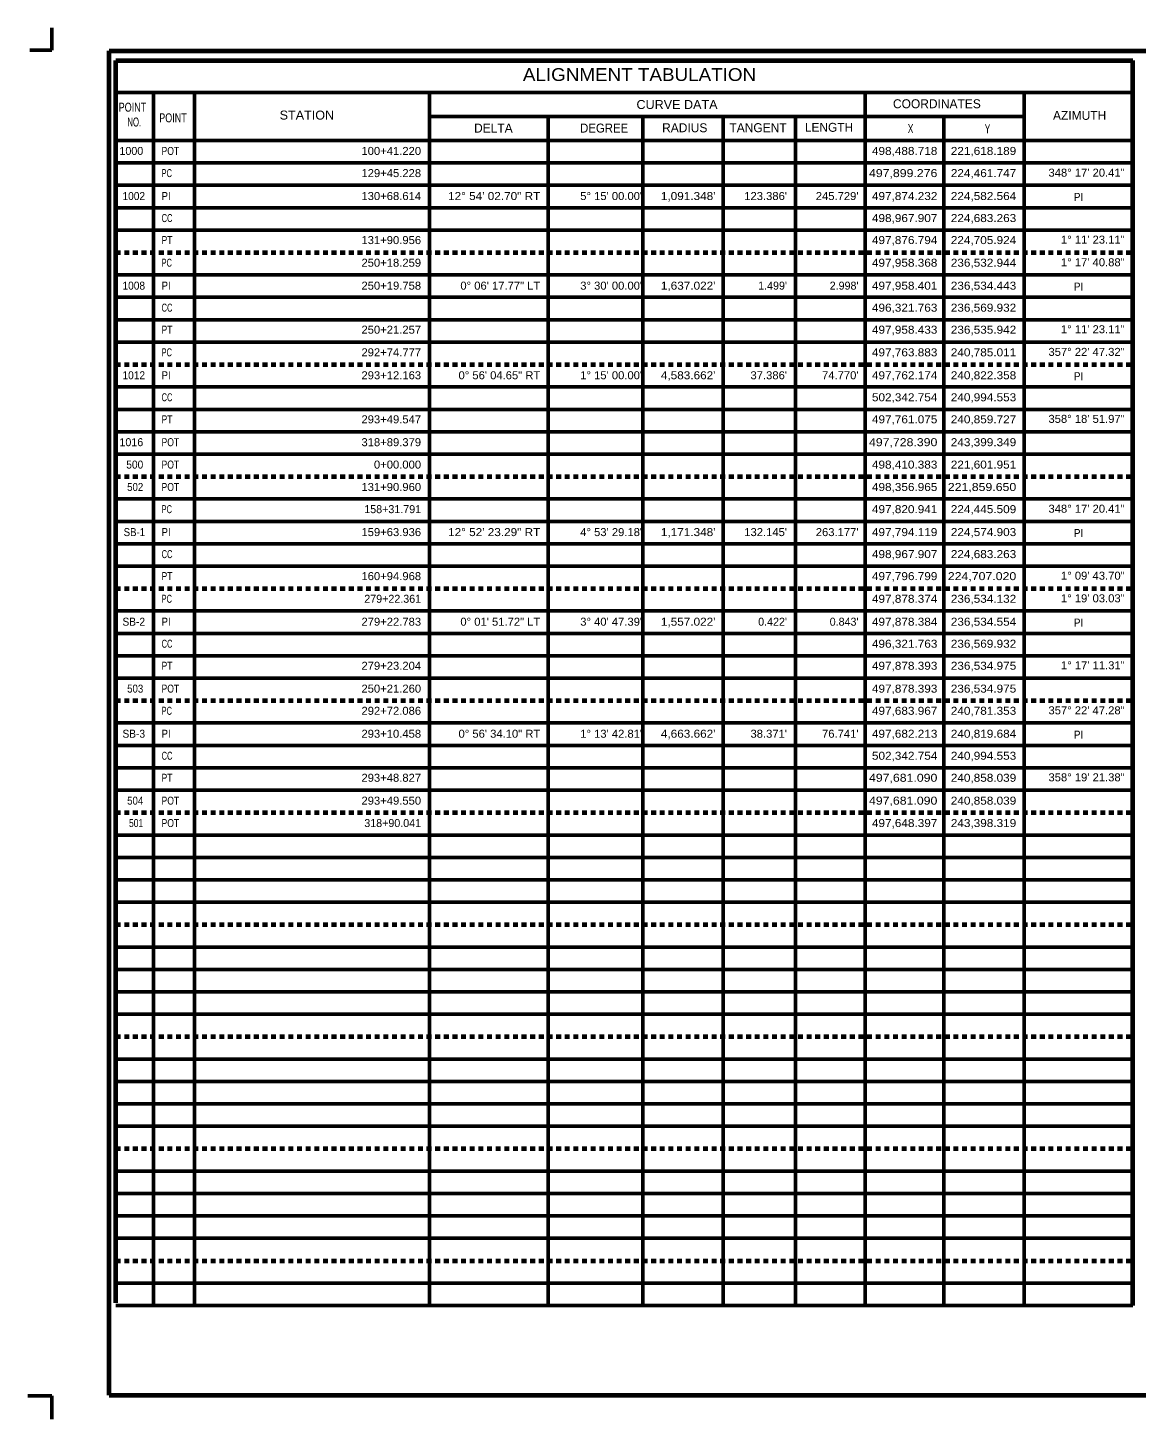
# Model space of a CAD drawing. Extents: x 22753 to 24440, y 5712 to 6801.
# Drawn here: x 22753 to 23619, y 5712 to 6799 of the extents above; entities that cross this region are included whole.
import ezdxf
from ezdxf.enums import TextEntityAlignment as Align

# ---------------------------------------------------------------- set-up
doc = ezdxf.new("R2010")
doc.units = 0
doc.header["$LTSCALE"] = 2.5
doc.linetypes.add('SHORT_DASHED', pattern=[2.7, 1.5, -1.2])
doc.layers.add('2', color=7, linetype='Continuous')
doc.layers.add('57', color=7, linetype='Continuous')
doc.layers.add('27', color=7, linetype='Continuous', lineweight=53)
doc.layers.add('63', color=7, linetype='Continuous', lineweight=70)

msp = doc.modelspace()

# ---------------------------------------------------------------- linework, layer by layer
at = {"layer": '27', "lineweight": 70}
for p, q in [((22821.896, 6773.426), (23616.896, 6773.426)), ((22821.896, 5803.105), (22821.896, 6773.426))]:
    msp.add_line(p, q, dxfattribs=at)
at = {"layer": '27'}
for p, q in [((22821.896, 6748.376), (23616.896, 6748.376)), ((22851.446, 6747.026), (22851.446, 5800.976)), ((22883.346, 6747.376), (22883.346, 5800.976)), ((23067.096, 6747.676), (23067.096, 5800.976)), ((23407.496, 6748.476), (23407.496, 5800.976)), ((23531.896, 6748.376), (23531.896, 5800.976)), ((23067.096, 6729.726), (23531.896, 6729.726)), ((23159.946, 6729.726), (23159.946, 5800.976)), ((23233.823, 6729.726), (23233.823, 5800.976)), ((23296.646, 6729.726), (23296.646, 5800.976)), ((23353.096, 6729.726), (23353.096, 5800.976)), ((23469.196, 6729.726), (23469.196, 5800.976)), ((22821.896, 6710.976), (23616.896, 6710.976)), ((22821.896, 6693.476), (23616.896, 6693.476)), ((22821.896, 6675.976), (23616.896, 6675.976)), ((22821.896, 6658.476), (23616.896, 6658.476)), ((22821.896, 6658.476), (23616.896, 6658.476)), ((22821.896, 6640.976), (23616.896, 6640.976)), ((22821.896, 6605.976), (23616.896, 6605.976)), ((22821.896, 6588.476), (23616.896, 6588.476)), ((22821.896, 6570.976), (23616.896, 6570.976)), ((22821.896, 6553.476), (23616.896, 6553.476)), ((22821.896, 6518.476), (23616.896, 6518.476)), ((22821.896, 6500.976), (23616.896, 6500.976)), ((22821.896, 6483.476), (23616.896, 6483.476)), ((22821.896, 6465.976), (23616.896, 6465.976)), ((22821.896, 6430.976), (23616.896, 6430.976)), ((22821.896, 6413.476), (23616.896, 6413.476)), ((22821.896, 6395.976), (23616.896, 6395.976)), ((22821.896, 6378.476), (23616.896, 6378.476)), ((22821.896, 6343.476), (23616.896, 6343.476)), ((22821.896, 6325.976), (23616.896, 6325.976)), ((22821.896, 6308.476), (23616.896, 6308.476)), ((22821.896, 6290.976), (23616.896, 6290.976)), ((22821.896, 6255.976), (23616.896, 6255.976)), ((22821.896, 6238.476), (23616.896, 6238.476)), ((22821.896, 6220.976), (23616.896, 6220.976)), ((22821.896, 6203.476), (23616.896, 6203.476)), ((22821.896, 6168.476), (23616.896, 6168.476)), ((22821.896, 6150.976), (23616.896, 6150.976)), ((22821.896, 6133.476), (23616.896, 6133.476)), ((22821.896, 6115.976), (23616.896, 6115.976)), ((22821.896, 6080.976), (23616.896, 6080.976)), ((22821.896, 6063.476), (23616.896, 6063.476)), ((22821.896, 6045.976), (23616.896, 6045.976)), ((22821.896, 6028.476), (23616.896, 6028.476)), ((22821.896, 5993.476), (23616.896, 5993.476)), ((22821.896, 5975.976), (23616.896, 5975.976)), ((22821.896, 5958.476), (23616.896, 5958.476)), ((22821.896, 5940.976), (23616.896, 5940.976)), ((22821.896, 5905.976), (23616.896, 5905.976)), ((22821.896, 5888.476), (23616.896, 5888.476)), ((22821.896, 5870.976), (23616.896, 5870.976)), ((22821.896, 5853.476), (23616.896, 5853.476)), ((22821.896, 5818.476), (23616.896, 5818.476)), ((22821.896, 5800.976), (23616.896, 5800.976))]:
    msp.add_line(p, q, dxfattribs=at)
at = {"layer": '27', "linetype": 'SHORT_DASHED', "lineweight": 70}
for p, q in [((22821.896, 6623.476), (23616.896, 6623.476)), ((22821.896, 6535.976), (23616.896, 6535.976)), ((22821.896, 6448.476), (23616.896, 6448.476)), ((22821.896, 6360.976), (23616.896, 6360.976)), ((22821.896, 6273.476), (23616.896, 6273.476)), ((22821.896, 6185.976), (23616.896, 6185.976)), ((22821.896, 6098.476), (23616.896, 6098.476)), ((22821.896, 6010.976), (23616.896, 6010.976)), ((22821.896, 5923.476), (23616.896, 5923.476)), ((22821.896, 5835.976), (23616.896, 5835.976))]:
    msp.add_line(p, q, dxfattribs=at)
at = {"layer": '63', "lineweight": 53}
for p, q in [((22771.946, 6798.981), (22771.946, 6781.476)), ((22754.874, 6781.476), (22771.946, 6781.476)), ((22753.209, 5730.476), (22771.946, 5730.476)), ((22771.946, 5712.174), (22771.946, 5730.476))]:
    msp.add_line(p, q, dxfattribs=at)
at = {"layer": '63'}
for p, q in [((22816.896, 6780.976), (24421.896, 6780.976)), ((22816.896, 5730.976), (22816.896, 6780.976)), ((23616.896, 5800.976), (23616.896, 6773.426)), ((22816.896, 5730.976), (24421.896, 5730.976))]:
    msp.add_line(p, q, dxfattribs=at)

# ---------------------------------------------------------------- texts
at = {"layer": '2'}
for s, p in [('1000', (22843.413, 6699.694)), ("1.499'", (23346.49, 6594.464)), ("2.998'", (23402.387, 6594.464)), ('1016', (22843.413, 6472.194)), ('158+31.791', (23060.553, 6419.88)), ('279+22.361', (23060.553, 6349.88)), ("0.422'", (23346.49, 6331.964)), ("0.843'", (23402.387, 6331.964)), ('318+90.041', (23060.553, 6174.694))]:
    msp.add_text(s, height=6.25, dxfattribs=at).set_placement(p, align=Align.RIGHT)
for s, width, p in [('POT', 0.8, (22857.746, 6699.694)), ('PC', 0.7, (22857.746, 6682.38)), ('PI', 0.9, (22857.746, 6664.464)), ('CC', 0.65, (22857.746, 6647.265)), ('PT', 0.8, (22857.746, 6630.065)), ('PC', 0.7, (22857.746, 6612.38)), ('PI', 0.9, (22857.746, 6594.464)), ('CC', 0.65, (22857.746, 6577.265)), ('PT', 0.8, (22857.746, 6560.065)), ('PC', 0.7, (22857.746, 6542.38)), ('PI', 0.9, (22857.746, 6524.464)), ('CC', 0.65, (22857.746, 6507.265)), ('PT', 0.8, (22857.746, 6490.065)), ('POT', 0.8, (22857.746, 6472.194)), ('POT', 0.8, (22857.746, 6454.694)), ('POT', 0.8, (22857.746, 6437.194)), ('PC', 0.7, (22857.746, 6419.88)), ('PI', 0.9, (22857.746, 6401.964)), ('CC', 0.65, (22857.746, 6384.765)), ('PT', 0.8, (22857.746, 6367.565)), ('PC', 0.7, (22857.746, 6349.88)), ('PI', 0.9, (22857.746, 6331.964)), ('CC', 0.65, (22857.746, 6314.765)), ('PT', 0.8, (22857.746, 6297.565)), ('POT', 0.8, (22857.746, 6279.694)), ('PC', 0.7, (22857.746, 6262.38)), ('PI', 0.9, (22857.746, 6244.464)), ('CC', 0.65, (22857.746, 6227.265)), ('PT', 0.8, (22857.746, 6210.065)), ('POT', 0.8, (22857.746, 6192.194)), ('POT', 0.8, (22857.746, 6174.694))]:
    msp.add_text(s, height=6.25, dxfattribs=dict(at, width=width)).set_placement(p)
for s, width, p in [('100+41.220', 1.05, (23060.553, 6699.694)), ('498,488.718', 1.1, (23464.018, 6699.694)), ('221,618.189', 1.1, (23525.648, 6699.694)), ('129+45.228', 1.05, (23060.553, 6682.38)), ('497,899.276', 1.15, (23464.018, 6682.38)), ('224,461.747', 1.1, (23525.648, 6682.38)), ('348° 17\' 20.41"', 1.05, (23610.378, 6682.735)), ('1002', 0.95, (22844.847, 6664.464)), ('130+68.614', 1.05, (23060.553, 6664.464)), ('12° 54\' 02.70" RT', 1.1, (23153.716, 6664.464)), ('5° 15\' 00.00"', 1.05, (23234.695, 6664.464)), ("1,091.348'", 1.1, (23290.592, 6664.464)), ("123.386'", 1.05, (23346.49, 6664.464)), ("245.729'", 1.05, (23402.387, 6664.464)), ('497,874.232', 1.1, (23464.018, 6664.464)), ('224,582.564', 1.1, (23525.648, 6664.464)), ('498,967.907', 1.1, (23464.018, 6647.265)), ('224,683.263', 1.1, (23525.648, 6647.265)), ('131+90.956', 1.05, (23060.553, 6630.065)), ('497,876.794', 1.1, (23464.018, 6630.065)), ('224,705.924', 1.1, (23525.648, 6630.065)), ('1° 11\' 23.11"', 1.05, (23610.378, 6630.406)), ('250+18.259', 1.05, (23060.553, 6612.38)), ('497,958.368', 1.1, (23464.018, 6612.38)), ('236,532.944', 1.1, (23525.648, 6612.38)), ('1° 17\' 40.88"', 1.05, (23610.378, 6612.735)), ('1008', 0.95, (22844.847, 6594.464)), ('250+19.758', 1.05, (23060.553, 6594.464)), ('0° 06\' 17.77" LT', 1.05, (23153.716, 6594.464)), ('3° 30\' 00.00"', 1.05, (23234.695, 6594.464)), ("1,637.022'", 1.1, (23290.592, 6594.464)), ('497,958.401', 1.1, (23464.018, 6594.464)), ('236,534.443', 1.1, (23525.648, 6594.464)), ('496,321.763', 1.1, (23464.018, 6577.265)), ('236,569.932', 1.1, (23525.648, 6577.265)), ('250+21.257', 1.05, (23060.553, 6560.065)), ('497,958.433', 1.1, (23464.018, 6560.065)), ('236,535.942', 1.1, (23525.648, 6560.065)), ('1° 11\' 23.11"', 1.05, (23610.378, 6560.406)), ('292+74.777', 1.05, (23060.553, 6542.38)), ('497,763.883', 1.1, (23464.018, 6542.38)), ('240,785.011', 1.1, (23525.648, 6542.38)), ('357° 22\' 47.32"', 1.05, (23610.378, 6542.735)), ('1012', 0.95, (22844.847, 6524.464)), ('293+12.163', 1.05, (23060.553, 6524.464)), ('0° 56\' 04.65" RT', 1.05, (23153.716, 6524.464)), ('1° 15\' 00.00"', 1.05, (23234.695, 6524.464)), ("4,583.662'", 1.1, (23290.592, 6524.464)), ("37.386'", 1.05, (23346.49, 6524.464)), ("74.770'", 1.05, (23402.387, 6524.464)), ('497,762.174', 1.1, (23464.018, 6524.464)), ('240,822.358', 1.1, (23525.648, 6524.464)), ('502,342.754', 1.1, (23464.018, 6507.265)), ('240,994.553', 1.1, (23525.648, 6507.265)), ('293+49.547', 1.05, (23060.553, 6490.065)), ('497,761.075', 1.1, (23464.018, 6490.065)), ('240,859.727', 1.1, (23525.648, 6490.065)), ('358° 18\' 51.97"', 1.05, (23610.378, 6490.406)), ('318+89.379', 1.05, (23060.553, 6472.194)), ('497,728.390', 1.15, (23464.018, 6472.194)), ('243,399.349', 1.1, (23525.648, 6472.194)), ('500', 0.95, (22843.413, 6454.694)), ('0+00.000', 1.05, (23060.553, 6454.694)), ('498,410.383', 1.1, (23464.018, 6454.694)), ('221,601.951', 1.1, (23525.648, 6454.694)), ('502', 0.9, (22843.413, 6437.194)), ('131+90.960', 1.05, (23060.553, 6437.194)), ('498,356.965', 1.1, (23464.018, 6437.194)), ('221,859.650', 1.15, (23525.648, 6437.194)), ('497,820.941', 1.1, (23464.018, 6419.88)), ('224,445.509', 1.1, (23525.648, 6419.88)), ('348° 17\' 20.41"', 1.05, (23610.378, 6420.235)), ('SB-1', 0.9, (22844.847, 6401.964)), ('159+63.936', 1.05, (23060.553, 6401.964)), ('12° 52\' 23.29" RT', 1.1, (23153.716, 6401.964)), ('4° 53\' 29.18"', 1.05, (23234.695, 6401.964)), ("1,171.348'", 1.1, (23290.592, 6401.964)), ("132.145'", 1.05, (23346.49, 6401.964)), ("263.177'", 1.05, (23402.387, 6401.964)), ('497,794.119', 1.1, (23464.018, 6401.964)), ('224,574.903', 1.1, (23525.648, 6401.964)), ('498,967.907', 1.1, (23464.018, 6384.765)), ('224,683.263', 1.1, (23525.648, 6384.765)), ('160+94.968', 1.05, (23060.553, 6367.565)), ('497,796.799', 1.1, (23464.018, 6367.565)), ('224,707.020', 1.15, (23525.648, 6367.565)), ('1° 09\' 43.70"', 1.05, (23610.378, 6367.906)), ('497,878.374', 1.1, (23464.018, 6349.88)), ('236,534.132', 1.1, (23525.648, 6349.88)), ('1° 19\' 03.03"', 1.05, (23610.378, 6350.235)), ('SB-2', 0.95, (22844.847, 6331.964)), ('279+22.783', 1.05, (23060.553, 6331.964)), ('0° 01\' 51.72" LT', 1.05, (23153.716, 6331.964)), ('3° 40\' 47.39"', 1.05, (23234.695, 6331.964)), ("1,557.022'", 1.1, (23290.592, 6331.964)), ('497,878.384', 1.1, (23464.018, 6331.964)), ('236,534.554', 1.1, (23525.648, 6331.964)), ('496,321.763', 1.1, (23464.018, 6314.765)), ('236,569.932', 1.1, (23525.648, 6314.765)), ('279+23.204', 1.05, (23060.553, 6297.565)), ('497,878.393', 1.1, (23464.018, 6297.565)), ('236,534.975', 1.1, (23525.648, 6297.565)), ('1° 17\' 11.31"', 1.05, (23610.378, 6297.906)), ('503', 0.9, (22843.413, 6279.694)), ('250+21.260', 1.05, (23060.553, 6279.694)), ('497,878.393', 1.1, (23464.018, 6279.694)), ('236,534.975', 1.1, (23525.648, 6279.694)), ('292+72.086', 1.05, (23060.553, 6262.38)), ('497,683.967', 1.1, (23464.018, 6262.38)), ('240,781.353', 1.1, (23525.648, 6262.38)), ('357° 22\' 47.28"', 1.05, (23610.378, 6262.735)), ('SB-3', 0.95, (22844.847, 6244.464)), ('293+10.458', 1.05, (23060.553, 6244.464)), ('0° 56\' 34.10" RT', 1.05, (23153.716, 6244.464)), ('1° 13\' 42.81"', 1.05, (23234.695, 6244.464)), ("4,663.662'", 1.1, (23290.592, 6244.464)), ("38.371'", 1.05, (23346.49, 6244.464)), ("76.741'", 1.05, (23402.387, 6244.464)), ('497,682.213', 1.1, (23464.018, 6244.464)), ('240,819.684', 1.1, (23525.648, 6244.464)), ('502,342.754', 1.1, (23464.018, 6227.265)), ('240,994.553', 1.1, (23525.648, 6227.265)), ('358° 19\' 21.38"', 1.05, (23610.378, 6210.406)), ('293+48.827', 1.05, (23060.553, 6210.065)), ('497,681.090', 1.15, (23464.018, 6210.065)), ('240,858.039', 1.1, (23525.648, 6210.065)), ('504', 0.9, (22843.413, 6192.194)), ('293+49.550', 1.05, (23060.553, 6192.194)), ('497,681.090', 1.15, (23464.018, 6192.194)), ('240,858.039', 1.1, (23525.648, 6192.194)), ('501', 0.8, (22843.413, 6174.694)), ('497,648.397', 1.1, (23464.018, 6174.694)), ('243,398.319', 1.1, (23525.648, 6174.694))]:
    msp.add_text(s, height=6.25, dxfattribs=dict(at, width=width)).set_placement(p, align=Align.RIGHT)
at = {"layer": '2', "width": 0.9}
for p in [(23574.378, 6663.747), (23574.378, 6593.747), (23574.378, 6523.747), (23574.378, 6401.247), (23574.378, 6331.247), (23574.378, 6243.747)]:
    msp.add_text('PI', height=6.25, dxfattribs=at).set_placement(p, align=Align.CENTER)
at = {"layer": '27', "width": 0.75}
for p in [(22834.959, 6733.476), (22866.66, 6725.176)]:
    msp.add_text('POINT', height=7, dxfattribs=at).set_placement(p, align=Align.CENTER)
at = {"layer": '27', "width": 0.65}
msp.add_text('NO.', height=7, dxfattribs=at).set_placement((22830.996, 6721.926))
at = {"layer": '57'}
for s, height, width, p in [('ALIGNMENT TABULATION', 10, 1.1, (23231.237, 6757.476)), ('CURVE DATA', 7, 1.05, (23260.553, 6735.576)), ('STATION', 7, 1.05, (22971.309, 6727.326)), ('DEGREE', 7, 0.95, (23203.6, 6717.176))]:
    msp.add_text(s, height=height, dxfattribs=dict(at, width=width)).set_placement(p, align=Align.CENTER)
for s, p in [('COORDINATES', (23463.645, 6736.176)), ('AZIMUTH', (23575.192, 6727.126)), ('DELTA', (23117.041, 6717.176)), ('RADIUS', (23266.599, 6717.426)), ('TANGENT', (23323.881, 6717.476))]:
    msp.add_text(s, height=7, dxfattribs=at).set_placement(p, align=Align.CENTER)
msp.add_text('LENGTH', height=6.95, dxfattribs=at).set_placement((23398.183, 6717.776), align=Align.RIGHT)
at = {"layer": '57', "width": 0.7}
for s, p in [('X', (23445.248, 6716.801)), ('Y', (23505.384, 6716.666))]:
    msp.add_text(s, height=6.95, dxfattribs=at).set_placement(p, align=Align.RIGHT)

doc.saveas('drawing.dxf')
